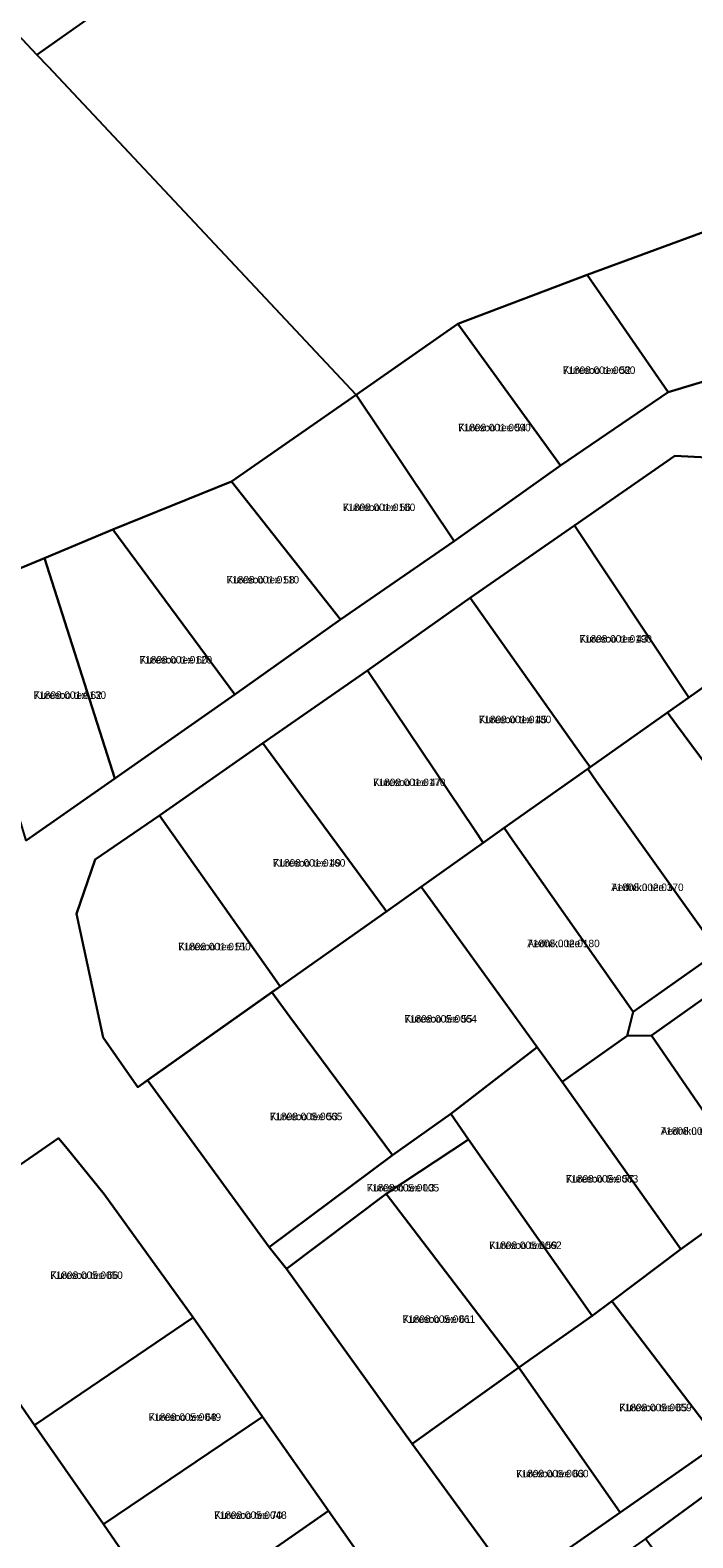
# Model space of a CAD drawing. Extents: x 529768 to 552006, y 6562269 to 6580975.
# Drawn here: x 536871 to 537003.6, y 6569673.6 to 6569975.7 of the extents above; entities that cross this region are included whole.
import ezdxf

# ---------------------------------------------------------------- set-up
doc = ezdxf.new("R2010")
doc.units = 0
for name, color, linetype in [('L_AADRESS', 7, 'Continuous'), ('PIIR', 7, 'Continuous'), ('TUNNUS', 7, 'Continuous')]:
    doc.layers.add(name, color=color, linetype=linetype)

msp = doc.modelspace()

# ---------------------------------------------------------------- linework, layer by layer
at = {"layer": 'PIIR'}
for points in [[(536541.11, 6569782.55), (536534.76, 6569778.12), (536458.07, 6569887.15), (536766.57, 6570096.71), (536793.41, 6570114.98), (536885.69, 6569984.15), (536887.53, 6569981.53), (536872.33, 6569970.82), (536848.17, 6569996.59)], [(536874.54, 6569968.46), (536872.33, 6569970.82), (537004.98, 6570064.24), (537087.96, 6570044.75), (537217.62, 6570003.73), (537216.26, 6569994.13), (537211.8, 6569990.69), (537189.74, 6569974.89), (537171.78, 6569962.1), (537154.21, 6569949.58), (537136.95, 6569937.29), (537135.14, 6569936.01), (537134.04, 6569937.57), (537117.07, 6569960.7), (537092.75, 6569993.55), (537071.26, 6569977.87), (537046.54, 6569959.99), (537019.53, 6569940.36), (536982.49, 6569926.7), (536956.57, 6569916.92), (536936.23, 6569902.65)], [(536593.31, 6569702.6), (536589.52, 6569700.23), (536551.32, 6569755.17), (536534.76, 6569778.12), (536541.11, 6569782.55), (536848.17, 6569996.59), (536872.33, 6569970.82), (536874.54, 6569968.46), (536936.23, 6569902.65), (536911.29, 6569885.33), (536887.5, 6569875.66), (536873.83, 6569869.95), (536855.43, 6569862.3), (536834.34, 6569853.6), (536743.48, 6569796.68)], [(536982.49, 6569926.7), (537019.53, 6569940.36), (537036.2, 6569914.4), (537015.35, 6569908.21), (536998.7, 6569903.2)], [(536956.57, 6569916.92), (536982.49, 6569926.7), (536998.7, 6569903.2), (536977.13, 6569888.51)], [(536936.23, 6569902.65), (536956.57, 6569916.92), (536977.13, 6569888.51), (536955.84, 6569873.36)], [(536911.29, 6569885.33), (536936.23, 6569902.65), (536955.84, 6569873.36), (536933.09, 6569857.63)], [(537001.14, 6569844.61), (536979.97, 6569876.46), (537000.05, 6569890.46), (537014.36, 6569889.68), (537031.65, 6569866.11), (537033.41, 6569863.68), (537016.43, 6569851.67), (537002.85, 6569842.04)], [(536887.5, 6569875.66), (536911.29, 6569885.33), (536933.09, 6569857.63), (536911.93, 6569842.6)], [(536873.83, 6569869.95), (536887.5, 6569875.66), (536911.93, 6569842.6), (536887.9, 6569825.79)], [(536959.04, 6569861.98), (536979.97, 6569876.46), (537001.14, 6569844.61), (537002.85, 6569842.04), (536998.59, 6569839.02), (536983.08, 6569828.05), (536981.24, 6569830.64)], [(536855.43, 6569862.3), (536873.83, 6569869.95), (536887.9, 6569825.79), (536870.16, 6569813.39)], [(536938.51, 6569847.41), (536959.04, 6569861.98), (536981.24, 6569830.64), (536983.08, 6569828.05), (536982.61, 6569827.71), (536965.89, 6569815.87), (536961.69, 6569812.9), (536959.97, 6569815.46)], [(536998.59, 6569839.02), (537002.85, 6569842.04), (537016.43, 6569851.67), (537018.21, 6569849.15), (537042.4, 6569814.87), (537025.31, 6569802.87), (537000.4, 6569836.57)], [(536938.51, 6569847.41), (536959.97, 6569815.46), (536961.69, 6569812.9), (536949.27, 6569804.1), (536942.29, 6569799.17), (536940.52, 6569801.59), (536917.57, 6569832.86)], [(536982.61, 6569827.71), (536983.08, 6569828.05), (536998.59, 6569839.02), (537000.4, 6569836.57), (537025.31, 6569802.87), (537008.71, 6569791.05), (536984.39, 6569825.21)], [(536896.86, 6569818.36), (536917.57, 6569832.86), (536940.52, 6569801.59), (536942.29, 6569799.17), (536921, 6569784.11), (536919.32, 6569786.49)], [(536965.89, 6569815.87), (536982.61, 6569827.71), (536984.39, 6569825.21), (537008.71, 6569791.05), (536991.72, 6569779.05), (536967.63, 6569813.38)], [(537062.94, 6569822.02), (537045.82, 6569810), (537028.9, 6569798.1), (537011.91, 6569786.06), (536995.4, 6569774.32), (536990.47, 6569774.25), (536991.72, 6569779.05), (537008.71, 6569791.05), (537025.31, 6569802.87), (537042.4, 6569814.87), (537059.3, 6569826.93)], [(536890.8, 6569766.42), (536885.56, 6569773.9), (536880.21, 6569798.68), (536883.99, 6569809.57), (536896.86, 6569818.36), (536919.32, 6569786.49), (536921, 6569784.11), (536892.53, 6569763.95)], [(536949.27, 6569804.1), (536961.69, 6569812.9), (536965.89, 6569815.87), (536967.63, 6569813.38), (536991.72, 6569779.05), (536990.47, 6569774.25), (536977.46, 6569765.04), (536951.05, 6569801.63)], [(536922.97, 6569778.06), (536919.36, 6569782.95), (536921, 6569784.11), (536942.29, 6569799.17), (536949.27, 6569804.1), (536951.05, 6569801.63), (536972.46, 6569771.96), (536955.2, 6569758.57), (536943.48, 6569750.32)], [(537011.91, 6569786.06), (537034.25, 6569754.81), (537016.97, 6569742.76), (536995.4, 6569774.32)], [(536897.12, 6569761.68), (536894.47, 6569765.32), (536919.36, 6569782.95), (536922.97, 6569778.06), (536943.48, 6569750.32), (536918.82, 6569731.85)], [(536995.4, 6569774.32), (537016.97, 6569742.76), (537009.13, 6569737.15), (537001.22, 6569731.49), (536977.46, 6569765.04), (536990.47, 6569774.25)], [(536955.2, 6569758.57), (536972.46, 6569771.96), (536977.46, 6569765.04), (537001.22, 6569731.49), (536987.43, 6569721.06), (536983.52, 6569718.1), (536958.72, 6569753.46)], [(536918.82, 6569731.85), (536943.48, 6569750.32), (536955.2, 6569758.57), (536958.72, 6569753.46), (536942.24, 6569742.59), (536922.29, 6569727.52)], [(536849.37, 6569728.66), (536846.43, 6569732.91), (536863.95, 6569744.99), (536876.62, 6569753.75), (536878.35, 6569751.64), (536885.77, 6569742.51), (536903.58, 6569717.8), (536871.82, 6569696.22)], [(536958.72, 6569753.46), (536983.52, 6569718.1), (536968.79, 6569707.74), (536942.24, 6569742.59)], [(536942.24, 6569742.59), (536968.79, 6569707.74), (536947.46, 6569692.48), (536922.29, 6569727.52)], [(537001.22, 6569731.49), (537009.13, 6569737.15), (537030.15, 6569707.21), (537009.06, 6569692.64), (536987.43, 6569721.06)], [(536806.18, 6569704.08), (536846.43, 6569732.91), (536849.37, 6569728.66), (536871.82, 6569696.22), (536885.63, 6569676.36), (536898.99, 6569656.96), (536911.84, 6569638.26), (536924.63, 6569620.03), (536934.36, 6569605.8), (536929.7, 6569603.34), (536911.36, 6569593.62), (536888.79, 6569581.54), (536921.53, 6569535.04), (536859.68, 6569503.73), (536751.37, 6569660.31), (536748.9, 6569663.88), (536802.92, 6569701.8)], [(536972.41, 6569658.2), (536968.13, 6569664.07), (536989.07, 6569678.69), (537009.06, 6569692.64), (537030.15, 6569707.21), (537051.45, 6569721.95), (537052.96, 6569719.78), (537055.02, 6569716.81), (537034.25, 6569702.21), (537013.11, 6569687.36), (536994.16, 6569673.46)], [(536968.79, 6569707.74), (536983.52, 6569718.1), (536987.43, 6569721.06), (537009.06, 6569692.64), (536989.07, 6569678.69)], [(536871.82, 6569696.22), (536903.58, 6569717.8), (536917.51, 6569697.9), (536885.63, 6569676.36)], [(536968.79, 6569707.74), (536989.07, 6569678.69), (536968.13, 6569664.07), (536947.46, 6569692.48)], [(536885.63, 6569676.36), (536917.51, 6569697.9), (536930.73, 6569679.02), (536898.99, 6569656.96)], [(537013.11, 6569687.36), (537035.22, 6569658.65), (537015.37, 6569644.51), (536994.16, 6569673.46)], [(536898.99, 6569656.96), (536930.73, 6569679.02), (536944.42, 6569659.45), (536911.84, 6569638.26)]]:
    msp.add_lwpolyline(points, close=True, dxfattribs=at)
for points in [[(536870.16, 6569813.39), (536887.9, 6569825.79), (536911.93, 6569842.6), (536933.09, 6569857.63), (536955.84, 6569873.36), (536977.13, 6569888.51), (536998.7, 6569903.2), (537015.35, 6569908.21)], [(537014.36, 6569889.68), (537000.05, 6569890.46), (536979.97, 6569876.46), (536959.04, 6569861.98), (536938.51, 6569847.41), (536917.57, 6569832.86), (536896.86, 6569818.36), (536883.99, 6569809.57), (536880.21, 6569798.68), (536885.56, 6569773.9), (536890.8, 6569766.42), (536892.53, 6569763.95), (536894.47, 6569765.32), (536897.12, 6569761.68), (536918.82, 6569731.85), (536922.29, 6569727.52), (536947.46, 6569692.48), (536968.13, 6569664.07)], [(536944.42, 6569659.45), (536930.73, 6569679.02), (536917.51, 6569697.9), (536903.58, 6569717.8), (536885.77, 6569742.51), (536878.35, 6569751.64), (536876.62, 6569753.75), (536863.95, 6569744.99)]]:
    msp.add_lwpolyline(points, dxfattribs=at)

# ---------------------------------------------------------------- texts
at = {"layer": 'L_AADRESS'}
for s, p in [('Kuresoo tee 52', (536977.64, 6569906.86)), ('Kuresoo tee 54', (536956.68, 6569895.36)), ('Kuresoo tee 56', (536933.57, 6569879.38)), ('Kuresoo tee 58', (536910.3, 6569864.87)), ('Kuresoo tee 43', (536980.95, 6569853.02)), ('Kuresoo tee 60', (536892.88, 6569848.83)), ('Kuresoo tee 62', (536871.66, 6569841.75)), ('Kuresoo tee 45', (536960.79, 6569836.87)), ('Kuresoo tee 47', (536939.63, 6569824.27)), ('Kuresoo tee 49', (536919.57, 6569808.13)), ('Aedniku tee 3', (536987.3, 6569803.24)), ('Kuresoo tee 51', (536900.61, 6569791.36)), ('Aedniku tee 1', (536970.5, 6569791.99)), ('Kuresoo tee 55', (536945.91, 6569776.88)), ('Kuresoo tee 53', (536918.97, 6569757.32)), ('Aedniku tee 2', (536997.21, 6569754.4)), ('Kuresoo tee 57', (536978.21, 6569744.83)), ('Kuresoo tee L3', (536938.35, 6569743.04)), ('Kuresoo tee 59', (536962.88, 6569731.51)), ('Kuresoo tee 66', (536875, 6569725.51)), ('Kuresoo tee 61', (536945.54, 6569716.71)), ('Kuresoo tee 65', (536988.93, 6569699)), ('Kuresoo tee 68', (536894.69, 6569697.08)), ('Kuresoo tee 63', (536968.27, 6569685.76)), ('Kuresoo tee 70', (536907.83, 6569677.43))]:
    msp.add_text(s, height=1.5, dxfattribs=at).set_placement(p)
at = {"layer": 'TUNNUS'}
for s, p in [('71808:001:0080', (536977.64, 6569906.86)), ('71808:001:0090', (536956.68, 6569895.36)), ('71808:001:0100', (536933.57, 6569879.38)), ('71808:001:0110', (536910.3, 6569864.87)), ('71808:001:0190', (536980.95, 6569853.02)), ('71808:001:0120', (536892.88, 6569848.83)), ('71808:001:0130', (536871.66, 6569841.75)), ('71808:001:0180', (536960.79, 6569836.87)), ('71808:001:0170', (536939.63, 6569824.27)), ('71808:001:0160', (536919.57, 6569808.13)), ('71808:002:0170', (536987.3, 6569803.24)), ('71808:001:0150', (536900.61, 6569791.36)), ('71808:002:0180', (536970.5, 6569791.99)), ('71808:005:0064', (536945.91, 6569776.88)), ('71808:005:0065', (536918.97, 6569757.32)), ('71808:002:0190', (536997.21, 6569754.4)), ('71808:005:0063', (536978.21, 6569744.83)), ('71808:005:0005', (536938.35, 6569743.04)), ('71808:005:0062', (536962.88, 6569731.51)), ('71808:005:0050', (536875, 6569725.51)), ('71808:005:0061', (536945.54, 6569716.71)), ('71808:005:0059', (536988.93, 6569699)), ('71808:005:0049', (536894.69, 6569697.08)), ('71808:005:0060', (536968.27, 6569685.76)), ('71808:005:0048', (536907.83, 6569677.43))]:
    msp.add_text(s, height=1.5, dxfattribs=at).set_placement(p)

doc.saveas('drawing.dxf')
